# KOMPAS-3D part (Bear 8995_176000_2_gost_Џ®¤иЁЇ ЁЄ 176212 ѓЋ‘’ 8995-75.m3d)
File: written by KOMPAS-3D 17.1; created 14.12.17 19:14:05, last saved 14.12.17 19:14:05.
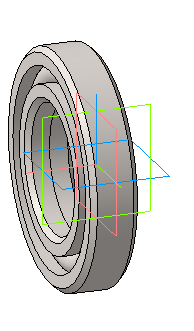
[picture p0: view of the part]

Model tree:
1. Операция без истории:1  (with: Операция без истории:2, Операция без истории:3, Операция без истории:4)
